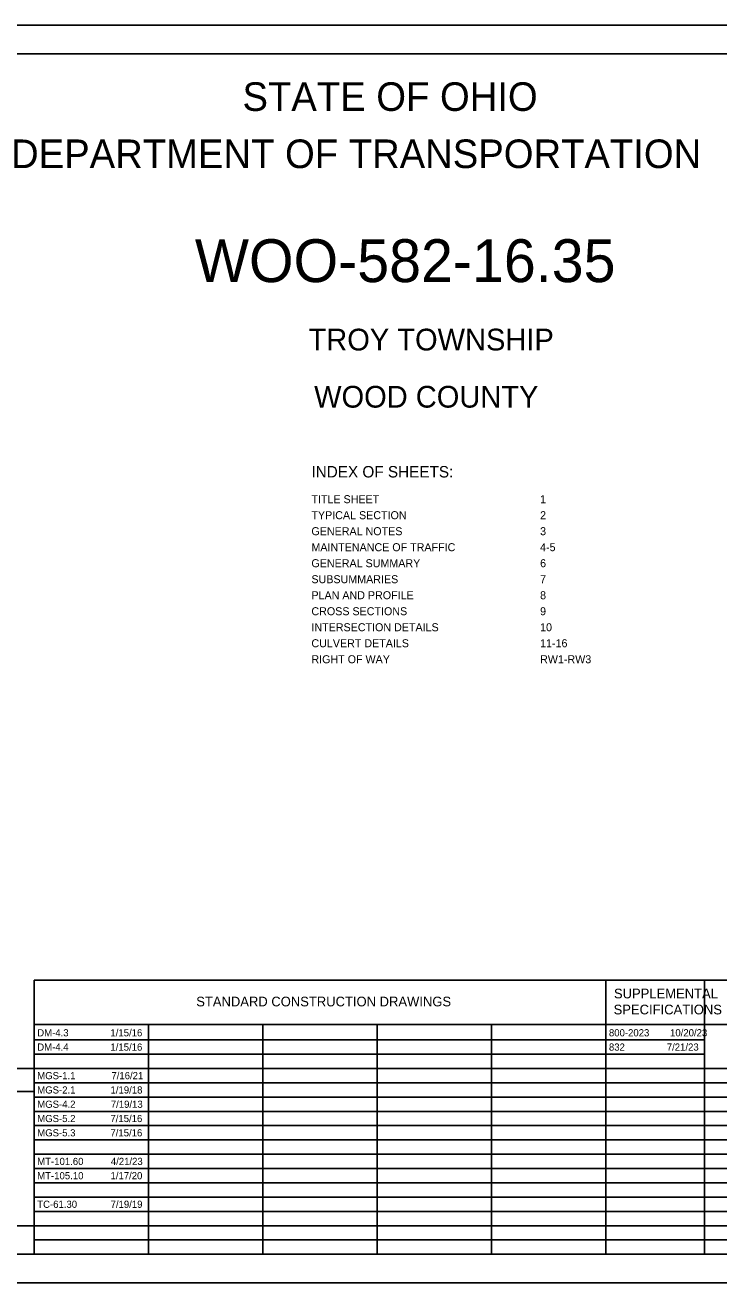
# Model space of a CAD drawing. Extents: x 0 to 34, y 0 to 22.
# Drawn here: x 9.99 to 22.13, y 0 to 22 of the extents above; entities that cross this region are included whole.
import ezdxf

# ---------------------------------------------------------------- set-up
doc = ezdxf.new("R2010")
doc.units = 0
for name, color, linetype in [('Default', 7, 'Continuous'), ('SH_Border', 7, 'Continuous'), ('SH_Cut_Line', 7, 'Continuous'), ('SH_Data', 7, 'Continuous'), ('SH_Text', 7, 'Continuous')]:
    doc.layers.add(name, color=color, linetype=linetype)

msp = doc.modelspace()

# ---------------------------------------------------------------- linework, layer by layer
at = {"layer": 'SH_Border'}
msp.add_lwpolyline([(1.5, 21.5), (33.5, 21.5), (33.5, 0.5), (1.5, 0.5)], close=True, dxfattribs=at)
at = {"layer": 'SH_Cut_Line'}
msp.add_lwpolyline([(0, 0), (34, 0), (34, 22), (0, 22)], close=True, dxfattribs=at)
at = {"layer": 'SH_Data'}
for p, q in [((10.15, 5.292), (23.6, 5.292)), ((10.15, 0.5), (10.15, 5.292)), ((20.15, 0.5), (20.15, 5.292)), ((21.875, 0.5), (21.875, 5.292)), ((10.15, 4.521), (23.6, 4.521)), ((12.15, 0.5), (12.15, 4.521)), ((14.15, 0.5), (14.15, 4.521)), ((16.15, 0.5), (16.15, 4.521)), ((18.15, 0.5), (18.15, 4.521)), ((10.15, 4.25), (21.875, 4.25)), ((10.15, 4), (21.875, 4)), ((10.15, 3.75), (7.35, 3.75)), ((10.15, 3.75), (23.6, 3.75)), ((10.15, 0.5), (10.15, 3.75)), ((10.15, 3.35), (7.35, 3.35)), ((10.15, 3.5), (23.6, 3.5)), ((10.15, 3.25), (23.6, 3.25)), ((10.15, 3), (23.6, 3)), ((10.15, 2.75), (23.6, 2.75)), ((10.15, 2.5), (23.6, 2.5)), ((10.15, 2.25), (23.6, 2.25)), ((10.15, 2), (23.6, 2)), ((10.15, 1.75), (23.6, 1.75)), ((10.15, 1.5), (23.6, 1.5)), ((10.15, 1.25), (23.6, 1.25)), ((10.15, 1), (23.6, 1)), ((10.15, 0.75), (23.6, 0.75)), ((10.15, 0.5), (7.35, 0.5))]:
    msp.add_line(p, q, dxfattribs=at)
msp.add_lwpolyline([(10.15, 0.5), (10.15, 1), (7.35, 1), (7.35, 0.5)], close=True, dxfattribs=at)

# ---------------------------------------------------------------- texts
at = {"layer": 'Default'}
for s, p in [('DM-4.3', (10.205, 4.312)), ('1/15/16', (11.485, 4.312)), ('800-2023', (20.205, 4.312)), ('10/20/23', (21.274, 4.312)), ('DM-4.4', (10.205, 4.062)), ('1/15/16', (11.485, 4.062)), ('832', (20.205, 4.062)), ('7/21/23', (21.217, 4.062)), ('MGS-1.1', (10.205, 3.562)), ('7/16/21', (11.502, 3.562)), ('MGS-2.1', (10.205, 3.312)), ('1/19/18', (11.487, 3.312)), ('MGS-4.2', (10.205, 3.062)), ('7/19/13', (11.492, 3.062)), ('MGS-5.2', (10.205, 2.812)), ('7/15/16', (11.485, 2.812)), ('MGS-5.3', (10.205, 2.562)), ('7/15/16', (11.485, 2.562)), ('MT-101.60', (10.205, 2.062)), ('4/21/23', (11.492, 2.062)), ('MT-105.10', (10.205, 1.812)), ('1/17/20', (11.486, 1.812)), ('TC-61.30', (10.205, 1.312)), ('7/19/19', (11.488, 1.312))]:
    msp.add_text(s, height=0.125, dxfattribs=at).set_placement(p)
at = {"layer": 'SH_Text'}
for s, height, p in [('STATE OF OHIO', 0.5, (13.795, 20.5)), ('DEPARTMENT OF TRANSPORTATION', 0.5, (9.747, 19.5)), ('WOO-582-16.35', 0.75, (12.962, 17.505)), ('TROY TOWNSHIP', 0.38, (14.95, 16.31)), ('WOOD COUNTY', 0.38, (15.048, 15.31)), ('INDEX OF SHEETS:', 0.2, (15.001, 14.088)), ('TITLE SHEET', 0.14, (15.001, 13.638)), ('1', 0.14, (19.001, 13.638)), ('TYPICAL SECTION', 0.14, (15.001, 13.358)), ('2', 0.14, (19.001, 13.358)), ('GENERAL NOTES', 0.14, (15.001, 13.078)), ('3', 0.14, (19.001, 13.078)), ('MAINTENANCE OF TRAFFIC', 0.14, (15.001, 12.798)), ('4-5', 0.14, (19.001, 12.798)), ('GENERAL SUMMARY', 0.14, (15.001, 12.518)), ('6', 0.14, (19.001, 12.518)), ('SUBSUMMARIES', 0.14, (15.001, 12.238)), ('7', 0.14, (19.001, 12.238)), ('PLAN AND PROFILE', 0.14, (15.001, 11.958)), ('8', 0.14, (19.001, 11.958)), ('CROSS SECTIONS', 0.14, (15.001, 11.678)), ('9', 0.14, (19.001, 11.678)), ('INTERSECTION DETAILS', 0.14, (15.001, 11.398)), ('10', 0.14, (19.001, 11.398)), ('CULVERT DETAILS', 0.14, (15.001, 11.118)), ('11-16', 0.14, (19.001, 11.118)), ('RIGHT OF WAY', 0.14, (15.001, 10.838)), ('RW1-RW3', 0.14, (19.001, 10.838)), ('SUPPLEMENTAL', 0.17, (20.293, 4.976)), ('STANDARD CONSTRUCTION DRAWINGS', 0.17, (12.986, 4.836)), ('SPECIFICATIONS', 0.17, (20.287, 4.696))]:
    msp.add_text(s, height=height, dxfattribs=at).set_placement(p)

doc.saveas('drawing.dxf')
